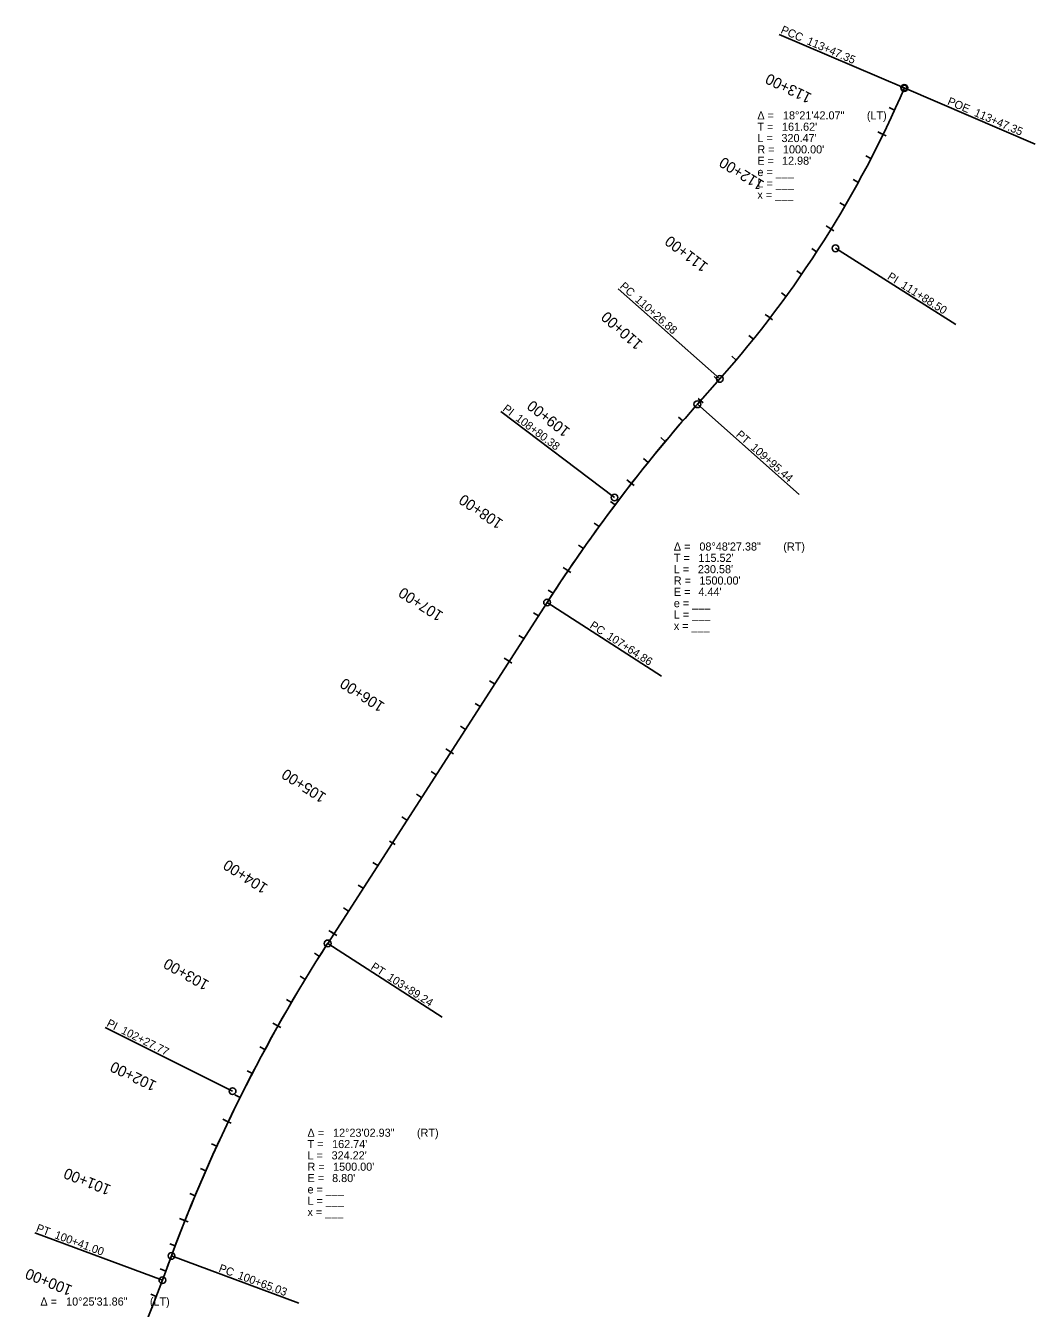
# Model space of a CAD drawing. Extents: x 14118486 to 14119897, y 8667783 to 8670021.
# Drawn here: x 14118962 to 14119897, y 8668833 to 8670021 of the extents above; entities that cross this region are included whole.
import ezdxf

# ---------------------------------------------------------------- set-up
doc = ezdxf.new("R2010")
doc.units = 0
for name, color, linetype in [('Alignment', 7, 'Continuous'), ('Draft_5', 7, 'Continuous'), ('TextAlignment', 7, 'Continuous'), ('TextAlignmentLrg', 7, 'Continuous'), ('TextAlignmentSml', 7, 'Continuous')]:
    doc.layers.add(name, color=color, linetype=linetype)

msp = doc.modelspace()

# ---------------------------------------------------------------- linework, layer by layer
at = {"layer": 'Alignment'}
for p, q in [((14119584, 8669670.3), (14119604.8, 8669693.8)), ((14119241.6, 8669170.9), (14119444.8, 8669486.7)), ((14119088.5, 8668858.9), (14119096.9, 8668881.4))]:
    msp.add_line(p, q, dxfattribs=at)
for centre, radius, start, end in [((14118856.6, 8670357.3), 1000, 318.435, 336.7966), ((14120706.3, 8668675.1), 1500, 138.435, 147.2426), ((14120503, 8668359.2), 1500, 147.2426, 159.6267), ((14117682.3, 8669381.1), 1500, 329.2012, 339.6267)]:
    msp.add_arc(centre, radius, start, end, dxfattribs=at)
at = {"layer": 'Draft_5'}
for p, q in [((14119241.6, 8669170.9), (14119444.8, 8669486.7)), ((14119092.9, 8668870.9), (14119096.9, 8668881.6))]:
    msp.add_line(p, q, dxfattribs=at)
for centre, radius, start, end in [((14118856.6, 8670357.3), 1000, 318.435, 336.7966), ((14120706.3, 8668675.1), 1500, 137.9326, 147.2426), ((14120706.3, 8668675.1), 1500, 138.435, 147.2426), ((14120503, 8668359.3), 1500, 147.2426, 159.6227), ((14120503, 8668359.2), 1500, 147.2426, 159.6267), ((14117682.3, 8669381.1), 1500, 329.2012, 339.6267)]:
    msp.add_arc(centre, radius, start, end, dxfattribs=at)
at = {"layer": 'TextAlignment'}
for p, q in [((14119775.7, 8669963.3), (14119659.9, 8670013)), ((14119659.9, 8670013), (14119659.9, 8670013)), ((14119775.7, 8669963.3), (14119897, 8669911.3)), ((14119897, 8669911.3), (14119897, 8669911.3)), ((14119712, 8669814.8), (14119823.5, 8669744.1)), ((14119604.8, 8669693.8), (14119510.5, 8669777.4)), ((14119510.5, 8669777.4), (14119510.5, 8669777.4)), ((14119823.5, 8669744.1), (14119823.5, 8669744.1)), ((14119584, 8669670.3), (14119678.2, 8669586.7)), ((14119507.3, 8669583.9), (14119402.1, 8669663.6)), ((14119402.1, 8669663.6), (14119402.1, 8669663.6)), ((14119678.2, 8669586.7), (14119678.2, 8669586.7)), ((14119444.8, 8669486.7), (14119550.8, 8669418.6)), ((14119550.8, 8669418.6), (14119550.8, 8669418.6)), ((14119241.6, 8669170.9), (14119347.5, 8669102.7)), ((14119347.5, 8669102.7), (14119347.5, 8669102.7)), ((14119153.5, 8669034), (14119035.4, 8669093)), ((14119035.4, 8669093), (14119035.4, 8669093)), ((14119088.5, 8668858.9), (14118970.4, 8668902.8)), ((14118970.4, 8668902.8), (14118970.4, 8668902.8)), ((14119096.9, 8668881.4), (14119215, 8668837.6)), ((14119215, 8668837.6), (14119215, 8668837.6))]:
    msp.add_line(p, q, dxfattribs=at)
for centre, radius in [((14119775.7, 8669963.3), 3.12), ((14119775.7, 8669963.3), 2.67), ((14119712, 8669814.8), 3.12), ((14119604.8, 8669693.8), 3.12), ((14119584, 8669670.3), 3.12), ((14119507.3, 8669583.9), 3.12), ((14119444.8, 8669486.7), 3.12), ((14119241.6, 8669170.9), 3.12), ((14119153.5, 8669034), 3.12), ((14119096.9, 8668881.4), 3.12), ((14119088.5, 8668858.9), 3.12)]:
    msp.add_circle(centre, radius, dxfattribs=at)
at = {"layer": 'TextAlignmentLrg'}
for p, q in [((14119756, 8669920.3), (14119751.1, 8669922.6)), ((14119707.9, 8669832.6), (14119703.3, 8669835.5)), ((14119651.3, 8669750.3), (14119646.9, 8669753.6)), ((14119584.7, 8669675.8), (14119589.3, 8669671.7)), ((14119523, 8669596.9), (14119518.6, 8669600.3)), ((14119464.2, 8669516.1), (14119459.6, 8669519.1)), ((14119409.7, 8669432.2), (14119405.1, 8669435.2)), ((14119355.6, 8669348.1), (14119351, 8669351.1)), ((14119298.9, 8669265.7), (14119304.1, 8669262.4)), ((14119247.4, 8669179.9), (14119242.8, 8669182.9)), ((14119195.5, 8669094.4), (14119190.8, 8669097.1)), ((14119149.5, 8669005.7), (14119144.5, 8669008)), ((14119109.4, 8668914.1), (14119104.3, 8668916.1))]:
    msp.add_line(p, q, dxfattribs=at)
at = {"layer": 'TextAlignmentSml'}
for p, q in [((14119766.7, 8669942.9), (14119761.7, 8669945.1)), ((14119753.3, 8669921.6), (14119758.8, 8669918.9)), ((14119744.8, 8669897.9), (14119740, 8669900.4)), ((14119733.1, 8669875.9), (14119728.3, 8669878.5)), ((14119720.8, 8669854.1), (14119716.1, 8669856.8)), ((14119705.3, 8669834.3), (14119710.5, 8669831)), ((14119694.5, 8669811.5), (14119690, 8669814.5)), ((14119680.6, 8669790.8), (14119676.1, 8669793.8)), ((14119666.2, 8669770.3), (14119661.8, 8669773.5)), ((14119648.9, 8669752.1), (14119653.7, 8669748.4)), ((14119635.9, 8669730.6), (14119631.6, 8669734)), ((14119620, 8669711.3), (14119615.8, 8669714.8)), ((14119603.6, 8669692.4), (14119599.5, 8669696.1)), ((14119584.7, 8669675.8), (14119589.3, 8669671.7)), ((14119570.5, 8669654.9), (14119566.4, 8669658.5)), ((14119554.3, 8669635.9), (14119550.1, 8669639.4)), ((14119538.5, 8669616.5), (14119534.2, 8669620)), ((14119520.5, 8669598.8), (14119525.4, 8669595.1)), ((14119507.8, 8669577.1), (14119503.4, 8669580.4)), ((14119492.9, 8669557), (14119488.5, 8669560.2)), ((14119478.4, 8669536.7), (14119473.9, 8669539.8)), ((14119461.6, 8669517.8), (14119466.7, 8669514.4)), ((14119450.3, 8669495.3), (14119445.8, 8669498.2)), ((14119436.8, 8669474.2), (14119432.2, 8669477.2)), ((14119423.2, 8669453.2), (14119418.7, 8669456.2)), ((14119407.1, 8669433.9), (14119412.3, 8669430.5)), ((14119396.2, 8669411.2), (14119391.6, 8669414.1)), ((14119382.7, 8669390.2), (14119378.1, 8669393.1)), ((14119369.1, 8669369.1), (14119364.5, 8669372.1)), ((14119353, 8669349.8), (14119358.2, 8669346.4)), ((14119342.1, 8669327.1), (14119337.5, 8669330)), ((14119328.6, 8669306.1), (14119324, 8669309)), ((14119315, 8669285), (14119310.4, 8669288)), ((14119298.9, 8669265.7), (14119304.1, 8669262.4)), ((14119288, 8669243), (14119283.4, 8669245.9)), ((14119274.4, 8669222), (14119269.9, 8669224.9)), ((14119260.9, 8669200.9), (14119256.3, 8669203.9)), ((14119244.8, 8669181.6), (14119250, 8669178.3)), ((14119233.9, 8669158.9), (14119229.3, 8669161.8)), ((14119220.8, 8669137.6), (14119216.1, 8669140.4)), ((14119208, 8669116.1), (14119203.3, 8669118.9)), ((14119192.9, 8669095.9), (14119198.2, 8669092.9)), ((14119183.5, 8669072.5), (14119178.7, 8669075.1)), ((14119171.8, 8669050.4), (14119166.9, 8669053)), ((14119160.4, 8669028.2), (14119155.5, 8669030.6)), ((14119146.7, 8669007), (14119152.2, 8669004.4)), ((14119138.9, 8668983), (14119133.9, 8668985.3)), ((14119128.7, 8668960.2), (14119123.7, 8668962.4)), ((14119118.9, 8668937.2), (14119113.8, 8668939.3)), ((14119106.6, 8668915.2), (14119112.3, 8668913)), ((14119100.4, 8668890.8), (14119095.3, 8668892.7)), ((14119091.6, 8668867.4), (14119086.5, 8668869.3)), ((14119082.8, 8668843.9), (14119077.7, 8668845.9))]:
    msp.add_line(p, q, dxfattribs=at)

# ---------------------------------------------------------------- texts
at = {"layer": 'TextAlignment'}
for s, rotation, p in [('PCC', 336.7966, (14119660.6, 8670014.5)), ('113+47.35', 336.7966, (14119684.7, 8670004.1)), ('POE ', 336.7966, (14119815, 8669948.3)), ('113+47.35', 336.7966, (14119839.7, 8669937.7)), ('PI ', 327.6158, (14119759.3, 8669786.8)), ('PC', 318.435, (14119511.6, 8669778.7)), ('111+88.50', 327.6158, (14119771.9, 8669778.8)), ('110+26.88', 318.435, (14119525.6, 8669766.3)), ('PI ', 322.8388, (14119403.1, 8669664.9)), ('108+80.38', 322.8388, (14119415, 8669655.9)), ('PT', 318.435, (14119619.2, 8669641.3)), ('109+95.44', 318.435, (14119632.8, 8669629.2)), ('PC', 327.2426, (14119483.7, 8669463.7)), ('107+64.86', 327.2426, (14119499.4, 8669453.6)), ('PT', 327.2426, (14119280.9, 8669147.5)), ('103+89.24', 327.2426, (14119296.1, 8669137.7)), ('PI ', 333.4346, (14119036.2, 8669094.5)), ('102+27.77', 333.4346, (14119049.6, 8669087.8)), ('PT', 339.6267, (14118970.9, 8668904.3)), ('100+41.00', 339.6267, (14118988, 8668898)), ('PC', 339.6267, (14119140.1, 8668867.1)), ('100+65.03', 339.6267, (14119157.6, 8668860.6))]:
    msp.add_text(s, height=7.5, rotation=rotation, dxfattribs=at).set_placement(p)
for s, p in [('Δ = ', (14119639.6, 8669934.2)), ('18°21\'42.07"', (14119663.3, 8669934.2)), (' (LT)', (14119738.2, 8669934.2)), ('T = ', (14119639.6, 8669923.7)), ("161.62'", (14119662.4, 8669923.7)), ('L = ', (14119639.6, 8669913.2)), ("320.47'", (14119661.9, 8669913.2)), ('R = ', (14119639.6, 8669902.7)), ("1000.00'", (14119663.3, 8669902.7)), ('E = ', (14119639.6, 8669892.2)), ("12.98'", (14119662.4, 8669892.2)), ('e = ___ ', (14119639.6, 8669881.7)), ('L = ___', (14119639.6, 8669871.2)), ('x = ___', (14119639.6, 8669860.7)), ('Δ = ', (14119562.2, 8669534.8)), ('08°48\'27.38"', (14119585.9, 8669534.8)), (' (RT)', (14119660.8, 8669534.8)), ('T = ', (14119562.2, 8669524.3)), ("115.52'", (14119585, 8669524.3)), ('L = ', (14119562.2, 8669513.8)), ("230.58'", (14119584.5, 8669513.8)), ('R = ', (14119562.2, 8669503.3)), ('E = ', (14119562.2, 8669492.8)), ("4.44'", (14119585, 8669492.8)), ("1500.00'", (14119585.9, 8669503.3)), ('e = ___ ', (14119562.2, 8669482.3)), ('L = ___', (14119562.2, 8669471.8)), ('x = ___', (14119562.2, 8669461.3)), ('T = ', (14119222.9, 8668981.3)), ('Δ = ', (14119222.9, 8668991.8)), ("162.74'", (14119245.7, 8668981.3)), ('12°23\'02.93"', (14119246.6, 8668991.8)), (' (RT)', (14119321.5, 8668991.8)), ('L = ', (14119222.9, 8668970.8)), ("324.22'", (14119245.2, 8668970.8)), ('R = ', (14119222.9, 8668960.3)), ("1500.00'", (14119246.6, 8668960.3)), ('E = ', (14119222.9, 8668949.8)), ("8.80'", (14119245.7, 8668949.8)), ('e = ___ ', (14119222.9, 8668939.3)), ('L = ___', (14119222.9, 8668928.8)), ('x = ___', (14119222.9, 8668918.3)), ('Δ = ', (14118975.5, 8668835.4)), ('10°25\'31.86"', (14118999.3, 8668835.4)), (' (LT)', (14119074.1, 8668835.4))]:
    msp.add_text(s, height=7.5, dxfattribs=at).set_placement(p)
at = {"layer": 'TextAlignmentLrg'}
for s, rotation, p in [('110+00', 138.435, (14119534.2, 8669727.2)), ('105+00', 147.2426, (14119241.1, 8669308.8)), ('100+00', 158.0607, (14119006, 8668853.4))]:
    msp.add_text(s, height=10.02, rotation=rotation, dxfattribs=at).set_placement(p)
at = {"layer": 'TextAlignmentSml'}
for s, rotation, p in [('113+00', 154.0836, (14119690.8, 8669957.5)), ('112+00', 148.3541, (14119646.7, 8669876.3)), ('111+00', 142.6245, (14119594.7, 8669799.8)), ('110+00', 138.435, (14119534.2, 8669727.2)), ('109+00', 142.0805, (14119466.9, 8669647)), ('108+00', 145.9003, (14119404.9, 8669562.3)), ('107+00', 147.2426, (14119349.4, 8669477)), ('106+00', 147.2426, (14119295.2, 8669392.9)), ('105+00', 147.2426, (14119241.1, 8669308.8)), ('104+00', 147.2426, (14119187, 8669224.7)), ('103+00', 150.6513, (14119132.6, 8669135.5)), ('102+00', 154.4711, (14119084, 8669042.5)), ('101+00', 158.2908, (14119041.6, 8668946.5)), ('100+00', 158.0607, (14119006, 8668853.4))]:
    msp.add_text(s, height=10.02, rotation=rotation, dxfattribs=at).set_placement(p)

doc.saveas('drawing.dxf')
